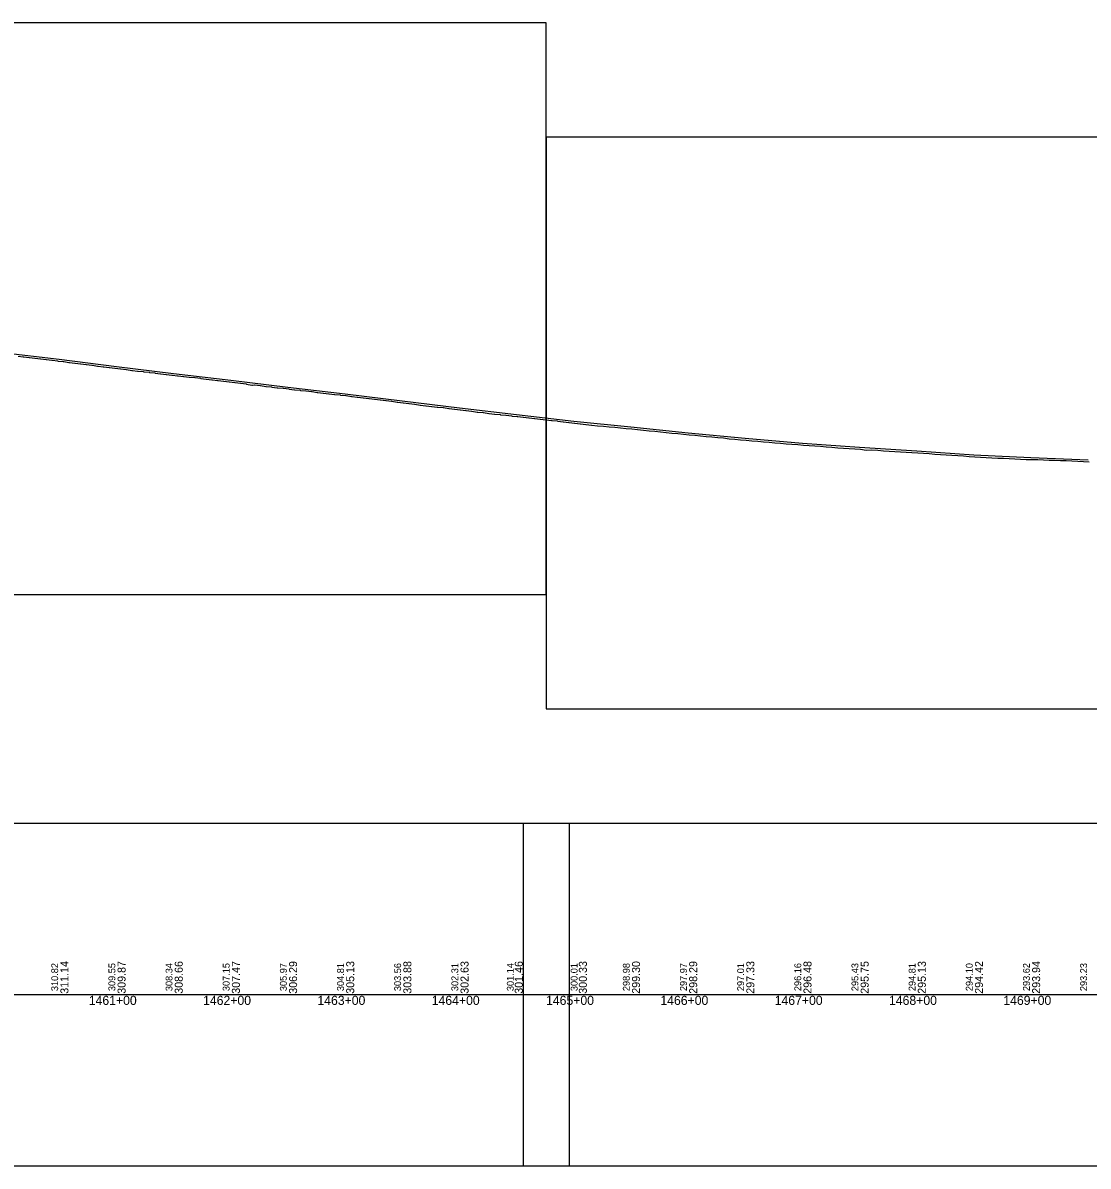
# Model space of a CAD drawing. Extents: x -3627 to 47473, y 2850 to 4350.
# Drawn here: x 33495 to 34427, y 2850 to 3850 of the extents above; entities that cross this region are included whole.
import ezdxf

# ---------------------------------------------------------------- set-up
doc = ezdxf.new("R2010")
doc.units = 0
for name, color, linetype in [('RD_DDB_Profile_EX', 7, 'Continuous'), ('RD_DDB_Profile_PR', 7, 'Continuous'), ('RD_DDB_StaTX', 7, 'Continuous'), ('RD_DDB_StripGrade', 7, 'Continuous'), ('RD_GPK_Profile_Cell', 7, 'Continuous'), ('RD_SHT_ShtClip', 7, 'Continuous')]:
    doc.layers.add(name, color=color, linetype=linetype)

msp = doc.modelspace()

# ---------------------------------------------------------------- linework, layer by layer
at = {"layer": 'RD_DDB_Profile_EX'}
for points in [[(33491.294025, 3558.50835), (33495.84544, 3557.86972), (33496.294737, 3557.824665)], [(33496.294737, 3557.824665), (33500.842267, 3557.368595), (33501.294386, 3557.301095), (33505.830307, 3556.66331), (33506.285847, 3556.59999), (33510.82841, 3556.144255), (33511.286449, 3556.11243), (33515.826105, 3555.566315), (33516.286998, 3555.497635), (33520.828381, 3554.90779), (33521.287022, 3554.848625), (33525.834799, 3554.259935), (33526.285675, 3554.21499), (33530.826594, 3553.760465), (33531.27661, 3553.7069), (33535.828842, 3553.02459), (33536.276689, 3552.957655), (33540.830678, 3552.45724), (33541.276717, 3552.404155), (33545.832913, 3551.766825), (33546.276798, 3551.71379), (33550.834739, 3551.167345), (33551.276929, 3551.10107), (33555.827001, 3550.55449), (33556.267896, 3550.501835), (33560.82882, 3549.772635), (33561.267147, 3549.711195), (33565.829361, 3549.25549), (33566.267228, 3549.19882), (33570.831179, 3548.51479), (33571.267359, 3548.475575), (33575.8326, 3547.928235), (33576.267491, 3547.871745), (33580.834022, 3547.415585), (33581.267573, 3547.368125), (33585.826655, 3546.86611), (33586.258573, 3546.801375), (33590.828073, 3546.02512), (33591.257842, 3545.9821), (33595.828628, 3545.43408), (33596.257876, 3545.387225), (33600.830821, 3544.93039), (33601.257959, 3544.883615), (33605.83675, 3544.33638), (33606.257475, 3544.28206), (33610.833837, 3543.77992), (33611.247872, 3543.73458), (33615.839748, 3543.093995), (33616.247377, 3543.041355), (33620.846019, 3542.445755), (33621.246929, 3542.39383), (33625.847791, 3541.8422), (33626.246967, 3541.806595), (33630.844784, 3541.30186), (33631.236481, 3541.25508), (33635.850234, 3540.795825), (33636.236036, 3540.74586), (33640.856122, 3540.239945), (33641.235547, 3540.187185), (33645.862344, 3539.72698), (33646.235189, 3539.69704), (33650.858259, 3539.09717), (33651.225568, 3539.045635), (33655.85934, 3538.258415), (33656.225738, 3538.21435), (33660.864581, 3537.798995), (33661.22464, 3537.759205), (33665.869128, 3537.204125), (33666.224273, 3537.14364), (33670.865075, 3536.495155), (33671.214608, 3536.456605), (33675.870376, 3535.94686), (33676.214224, 3535.89173), (33680.875698, 3535.33505), (33681.213161, 3535.311275), (33685.876137, 3534.845485), (33686.213329, 3534.79142), (33690.872116, 3534.14062), (33691.208922, 3534.110695), (33695.882722, 3533.13161), (33696.208437, 3533.09245), (33698.048957, 3533.417845), (33698.378889, 3533.38468), (33703.046293, 3532.774565), (33703.385522, 3532.733755), (33708.043035, 3531.93723), (33708.395655, 3531.89835), (33713.041046, 3531.523655), (33713.402253, 3531.48021), (33718.03906, 3530.82805), (33718.408837, 3530.783575), (33723.035834, 3530.40836), (33723.419172, 3530.369755), (33728.033756, 3529.76681), (33728.425727, 3529.696145), (33733.034268, 3529.05148), (33733.424566, 3529.0279), (33738.033999, 3528.61352), (33738.424184, 3528.550975), (33743.025279, 3528.09047), (33743.414616, 3528.047515)], [(33743.414616, 3528.047515), (33748.025792, 3527.49472), (33748.41423, 3527.447985), (33753.026306, 3526.710575), (33753.41355, 3526.660275), (33758.026925, 3526.2456), (33758.41287, 3526.20319), (33763.028795, 3525.651815), (33763.408702, 3525.602475), (33768.029414, 3524.909895), (33768.407552, 3524.87568), (33773.019916, 3524.506435), (33773.397664, 3524.457375), (33778.020536, 3523.995635), (33778.396982, 3523.946745), (33783.021156, 3523.29992), (33783.396584, 3523.266015), (33788.021674, 3522.711515), (33788.395901, 3522.66291), (33793.023552, 3521.92481), (33793.39171, 3521.88067), (33798.024173, 3521.417915), (33798.391026, 3521.37393), (33803.024793, 3520.91107), (33803.389614, 3520.867245), (33808.015399, 3520.40426), (33808.379698, 3520.367875), (33813.016019, 3519.672935), (33813.378739, 3519.625965), (33818.017999, 3519.07163), (33818.374269, 3519.014815), (33823.018716, 3518.36513), (33823.372879, 3518.33323), (33828.018628, 3517.683305), (33828.371932, 3517.641075), (33833.019347, 3517.083855), (33833.370988, 3517.034795), (33838.010752, 3516.47738), (33838.360348, 3516.428375), (33843.010672, 3515.731325), (33843.359407, 3515.672215), (33848.01266, 3515.162955), (33848.354965, 3515.132335), (33853.013375, 3514.434075), (33853.354287, 3514.38979), (33858.013997, 3513.97093), (33858.352679, 3513.93717), (33863.014034, 3513.471555), (33863.351751, 3513.427835), (33868.005409, 3512.82216), (33868.341787, 3512.77847), (33873.00603, 3512.032705), (33873.341364, 3511.98231), (33878.005289, 3511.46781), (33878.344448, 3511.43718), (33883.004547, 3510.8766), (33883.34685, 3510.83534), (33888.003112, 3510.32176), (33888.349927, 3510.280035), (33893.002363, 3509.580855), (33893.353003, 3509.54219), (33897.992309, 3509.16891), (33898.346826, 3509.12626), (33902.991568, 3508.42824), (33903.34991, 3508.37797), (33907.990827, 3507.86608), (33908.352995, 3507.82251), (33912.990086, 3507.31101), (33913.356079, 3507.274295), (33917.989345, 3506.76325), (33918.358427, 3506.71876), (33922.987856, 3506.161835), (33923.361504, 3506.116885), (33927.977848, 3505.652855), (33928.355088, 3505.611405), (33932.977211, 3505.101515), (33933.357884, 3505.059685), (33937.977831, 3504.45961), (33938.356925, 3504.41432), (33942.979812, 3504.00079), (33943.352223, 3503.960195), (33947.981893, 3503.499845), (33948.347804, 3503.456145), (33952.983872, 3502.809665), (33953.34267, 3502.76672), (33957.985143, 3502.305095), (33958.338265, 3502.26998), (33962.977816, 3501.76117), (33963.324329, 3501.719935), (33967.979888, 3501.16387), (33968.319916, 3501.126655), (33972.981865, 3500.569765), (33973.315502, 3500.52324), (33977.983843, 3499.96571), (33978.311089, 3499.939715), (33982.98582, 3499.38118), (33983.305797, 3499.3398), (33987.988535, 3498.782335), (33988.297904, 3498.74847), (33992.981118, 3498.23475), (33993.284145, 3498.204605)], [(33993.284145, 3498.204605), (33998.27951, 3497.51374), (34003.275318, 3497.157835), (34008.274647, 3496.799805), (34013.277498, 3496.309675), (34018.276828, 3495.90156), (34023.276157, 3495.20222), (34028.275271, 3494.850145), (34033.26464, 3494.397915), (34038.26397, 3493.80717), (34043.263301, 3493.29928), (34048.262631, 3492.755625), (34053.261961, 3492.2591), (34058.264813, 3491.80164), (34063.264144, 3491.15799), (34068.263265, 3490.755955), (34073.253406, 3490.250805), (34078.252945, 3489.75134), (34083.251925, 3489.254665), (34088.254781, 3488.750005), (34093.254322, 3488.308995), (34098.253861, 3487.8595), (34103.253399, 3487.4544), (34108.25626, 3486.905405), (34113.255799, 3486.220045), (34118.245726, 3485.862175), (34123.247812, 3485.413435), (34128.247142, 3484.96689), (34133.246261, 3484.51481), (34138.245382, 3484.012765), (34143.248021, 3483.65269), (34148.247354, 3483.159), (34153.246478, 3482.804175), (34158.245605, 3482.260565), (34163.244734, 3481.766895), (34168.234659, 3481.5092), (34173.233584, 3481.06288), (34178.232717, 3480.7582), (34183.231852, 3480.356295), (34188.23079, 3479.96534), (34193.229397, 3479.61611), (34198.228544, 3479.06688), (34203.227498, 3478.809845), (34208.22665, 3478.418545), (34213.225613, 3478.114215), (34218.224771, 3477.722795), (34223.223932, 3477.4658), (34228.223282, 3477.076725), (34233.216845, 3476.38795), (34238.216383, 3476.56761), (34243.215919, 3476.162955), (34248.218938, 3475.58196), (34253.218476, 3475.51412), (34258.221498, 3475.10953), (34263.220317, 3474.815475), (34268.219857, 3474.508105), (34273.222874, 3474.21675), (34278.222416, 3474.009285), (34283.221955, 3473.659815), (34288.224978, 3473.26588), (34293.224323, 3472.866515), (34298.223667, 3472.47246), (34303.223012, 3472.120425), (34308.212725, 3471.773785), (34313.215556, 3471.56945), (34318.2149, 3471.16742), (34323.214049, 3470.72346), (34328.213394, 3470.46882), (34333.212219, 3470.17467), (34338.211376, 3469.925405), (34343.214195, 3469.62374), (34348.213544, 3469.326965), (34353.212703, 3469.214665), (34358.212053, 3468.828275), (34363.207932, 3468.57603), (34368.207281, 3468.426645), (34373.20315, 3468.184505), (34378.202498, 3468.085095), (34383.192369, 3467.9381), (34388.188216, 3467.836125), (34393.187387, 3467.636845), (34398.183229, 3467.43744), (34403.182573, 3467.23806), (34408.178405, 3467.088795), (34413.177749, 3466.839425), (34418.177092, 3466.63786), (34423.172913, 3466.34095), (34428.172413, 3466.093615)]]:
    msp.add_lwpolyline(points, dxfattribs=at)
at = {"layer": 'RD_DDB_Profile_PR'}
msp.add_lwpolyline([(33477.33, 3561.813), (33527.33, 3555.7105), (33577.33, 3549.3655), (33627.33, 3543.2875), (33677.33, 3537.3585), (33727.33, 3531.459), (33777.33, 3525.6645), (33827.33, 3519.3795), (33877.33, 3513.1425), (33927.33, 3507.318), (33977.33, 3501.644), (34027.33, 3496.5165), (34077.33, 3491.4435), (34127.33, 3486.649), (34177.33, 3482.413), (34227.33, 3478.746), (34277.33, 3475.6465), (34327.33, 3472.114), (34377.33, 3469.7025), (34427.33, 3467.7355)], dxfattribs=at)
at = {"layer": 'RD_GPK_Profile_Cell'}
msp.add_line((1000, 3000), (46705.077602, 3000), dxfattribs=at)
at = {"layer": 'RD_SHT_ShtClip'}
for points in [[(32453.33, 3850), (32453.33, 3350), (33953.33, 3350), (33953.33, 3350), (33953.33, 3850), (33953.33, 3850)], [(33953.33, 3750), (33953.33, 3250), (35453.33, 3250), (35453.33, 3250), (35453.33, 3750), (35453.33, 3750)], [(32433.33, 3150), (33973.33, 3150), (33973.33, 2850), (32433.33, 2850)], [(33933.33, 3150), (35473.33, 3150), (35473.33, 2850), (33933.33, 2850)]]:
    msp.add_lwpolyline(points, close=True, dxfattribs=at)

# ---------------------------------------------------------------- texts
at = {"layer": 'RD_DDB_StaTX'}
for s, p in [('1461+00', (33553.125471, 2991)), ('1462+00', (33653.125471, 2991)), ('1463+00', (33753.125471, 2991)), ('1464+00', (33853.125471, 2991)), ('1465+00', (33953.125471, 2991)), ('1466+00', (34053.125471, 2991)), ('1467+00', (34153.125471, 2991)), ('1468+00', (34253.125471, 2991)), ('1469+00', (34353.125471, 2991))]:
    msp.add_text(s, height=8, dxfattribs=at).set_placement(p)
at = {"layer": 'RD_DDB_StripGrade'}
for s, height, p in [('310.82', 6, (33526.33, 3003.073688)), ('311.14', 7, (33535.33, 3000.75)), ('309.55', 6, (33576.33, 3003.073688)), ('309.87', 7, (33585.33, 3000.75)), ('308.34', 6, (33626.33, 3003.073688)), ('308.66', 7, (33635.33, 3000.75)), ('307.15', 6, (33676.33, 3003.073688)), ('307.47', 7, (33685.33, 3000.75)), ('305.97', 6, (33726.33, 3003.073688)), ('306.29', 7, (33735.33, 3000.75)), ('304.81', 6, (33776.33, 3003.073688)), ('305.13', 7, (33785.33, 3000.75)), ('303.56', 6, (33826.33, 3003.073688)), ('303.88', 7, (33835.33, 3000.75)), ('302.31', 6, (33876.33, 3003.073688)), ('302.63', 7, (33885.33, 3000.75)), ('301.14', 6, (33924.84657, 3003.073688)), ('301.46', 7, (33932.747393, 3000.75)), ('300.01', 6, (33980.690691, 3003.073688)), ('300.33', 7, (33988.83, 3000.75)), ('298.98', 6, (34026.33, 3003.073688)), ('299.30', 7, (34035.33, 3000.75)), ('297.97', 6, (34076.33, 3003.073688)), ('298.29', 7, (34085.33, 3000.75)), ('297.01', 6, (34126.33, 3003.073688)), ('297.33', 7, (34135.33, 3000.75)), ('296.16', 6, (34176.33, 3003.073688)), ('296.48', 7, (34185.33, 3000.75)), ('295.43', 6, (34226.33, 3003.073688)), ('295.75', 7, (34235.33, 3000.75)), ('294.81', 6, (34276.33, 3003.073688)), ('295.13', 7, (34285.33, 3000.75)), ('294.10', 6, (34326.33, 3003.073688)), ('294.42', 7, (34335.33, 3000.75)), ('293.62', 6, (34376.33, 3003.073688)), ('293.94', 7, (34385.33, 3000.75)), ('293.23', 6, (34426.33, 3003.073688))]:
    msp.add_text(s, height=height, rotation=90, dxfattribs=at).set_placement(p)

doc.saveas('drawing.dxf')
